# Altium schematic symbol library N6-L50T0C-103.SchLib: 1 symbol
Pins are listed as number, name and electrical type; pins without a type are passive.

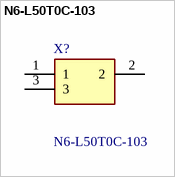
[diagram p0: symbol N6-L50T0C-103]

## N6-L50T0C-103
designator X?
Trimmer Resistors - Through Hole 10Kohms 6mm Top adj; Manufacturer_Name: Amphenol; Geometry.Height: 7.6mm
footprint N6L50T0C103
pins: 1, 2, 3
